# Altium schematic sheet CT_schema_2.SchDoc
size 176 x 135 mm
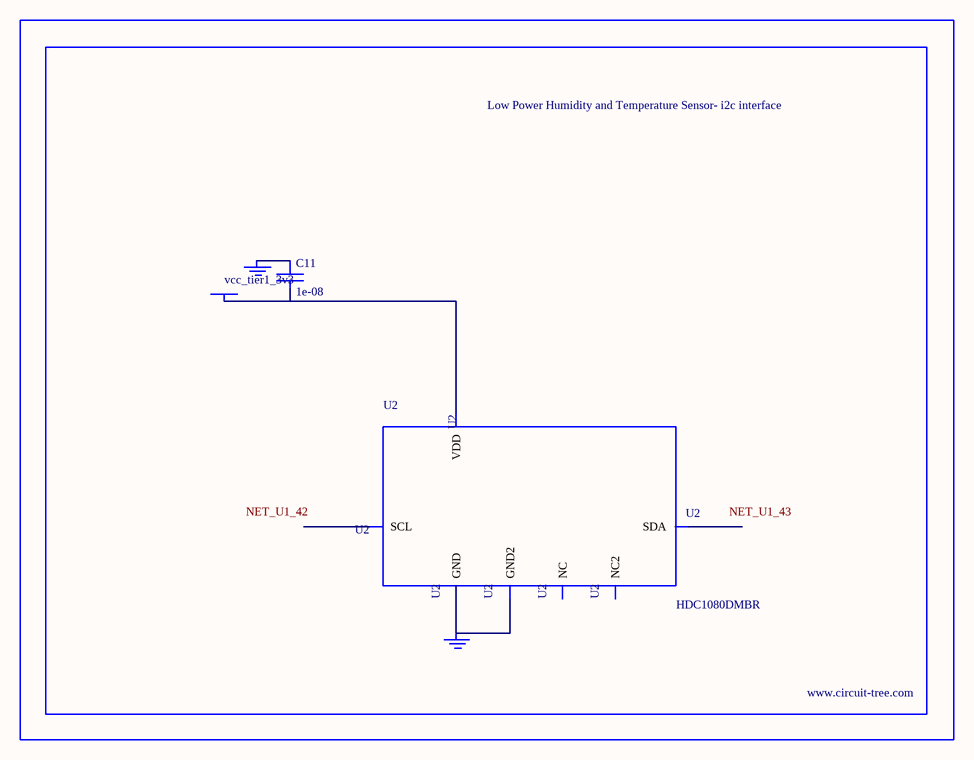
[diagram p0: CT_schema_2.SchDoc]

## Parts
BORDER1  (no value)
C11  1e-08  [C0402]
GND_INSTANCE_1_0  (no value)
GND_INSTANCE_1_1  (no value)
POWER_INSTANCE_1_0  vcc_tier1_3v3
U2  HDC1080DMBR  [WSON-6]

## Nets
NetC11_1: C11.1 GND_INSTANCE_1_0.0(GND)
NetC11_2: C11.2 POWER_INSTANCE_1_0.0(PWR) U2.5(VDD)
NetGND_INSTANCE_1_1_0: GND_INSTANCE_1_1.0(GND) U2.2(GND) U2.PAD(GND2)

Not connected (* = marked no-connect by the designer): U2 1(SDA) 3(NC) 4(NC2) 6(SCL)

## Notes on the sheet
- Labels drawn without touching a wire or pin: NET_U1_42, NET_U1_43

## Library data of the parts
BORDER1 = BORDER_PAGE1
C11 = C0402C103K3RAC
GND_INSTANCE_1_0 GND_INSTANCE_1_1 = GND
POWER_INSTANCE_1_0 = PWR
